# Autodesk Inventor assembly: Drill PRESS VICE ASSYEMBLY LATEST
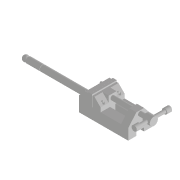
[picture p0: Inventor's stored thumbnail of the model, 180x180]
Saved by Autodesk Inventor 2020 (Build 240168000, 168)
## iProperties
Created: 2019-04
Part Number: Drill PRESS VICE ASSYEMBLY LATEST
Document SubType Name: Assembly
Designer: LENOVO-CADCIM
Author: LENOVO-CADCIM
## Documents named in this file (9)
- D:\Autodesk Inventor_2020\c10\c10_Inv_2019_tut\c10_Inv_tut_2019\c10_tut02_inv\Drill Press Vice\Drill Press Vice\Drill PRESS VICE ASSYEMBLY LATEST.iam
- D:\Autodesk Inventor_2020\c10\c10_Inv_2019_tut\c10_Inv_tut_2019\c10_tut02_inv\Drill Press Vice\Drill Press Vice\Base.ipt
- D:\Autodesk Inventor_2020\c10\c10_Inv_2019_tut\c10_Inv_tut_2019\c10_tut02_inv\Drill Press Vice\Drill Press Vice\Movable Jaw.ipt
- D:\Autodesk Inventor_2020\c10\c10_Inv_2019_tut\c10_Inv_tut_2019\c10_tut02_inv\Drill Press Vice\Drill Press Vice\Jaw Face.ipt
- D:\Autodesk Inventor_2020\c10\c10_Inv_2019_tut\c10_Inv_tut_2019\c10_tut02_inv\Drill Press Vice\Drill Press Vice\Cap Screw.ipt
- D:\Autodesk Inventor_2020\c10\c10_Inv_2019_tut\c10_Inv_tut_2019\c10_tut02_inv\Drill Press Vice\Drill Press Vice\Clamp Screw Handle.ipt
- D:\Autodesk Inventor_2020\c10\c10_Inv_2019_tut\c10_Inv_tut_2019\c10_tut02_inv\Drill Press Vice\Drill Press Vice\Clamp Screw.ipt
- D:\Autodesk Inventor_2020\c10\c10_Inv_2019_tut\c10_Inv_tut_2019\c10_tut02_inv\Drill Press Vice\Drill Press Vice\Safety Handle.ipt
- D:\Autodesk Inventor_2020\c10\c10_Inv_2019_tut\c10_Inv_tut_2019\c10_tut02_inv\Drill Press Vice\Drill Press Vice\Handle Stop.ipt
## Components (13 placed, 8 different names)
1. Base:1 — Mate:1, Mate:2, Insert:1, Insert:4, Insert:5, Mate:3, Mate:6, Mate:7
2. Movable Jaw:1 — Mate:1, Mate:2, Insert:2, Insert:3, Insert:6, Insert:7, Mate:4
3. Jaw Face:1 — Insert:1, Mate:8
4. Jaw Face:2 — Insert:2, Insert:3, Mate:8
5. Cap Screw:1 — Insert:4
6. Cap Screw:2 — Insert:7
7. Cap Screw:3 — Insert:5
8. Cap Screw:4 — Insert:6
9. Clamp Screw Handle:1 — Mate:5, Insert:8, Insert:9
10. Clamp Screw:1 — Mate:3, Mate:4, Mate:5
11. Safety Handle:1 — Mate:6, Mate:7
12. Handle Stop:1 — Insert:9
13. Handle Stop:2 — Insert:8
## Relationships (17: Insert 9, Mate 8)
- Mate:1: Base:1 ↔ Movable Jaw:1
- Mate:2: Base:1 ↔ Movable Jaw:1
- Insert:1: Base:1 ↔ Jaw Face:1
- Insert:2: Movable Jaw:1 ↔ Jaw Face:2
- Insert:3: Movable Jaw:1 ↔ Jaw Face:2
- Insert:4: Base:1 ↔ Cap Screw:1
- Insert:5: Base:1 ↔ Cap Screw:3
- Insert:6: Movable Jaw:1 ↔ Cap Screw:4
- Insert:7: Movable Jaw:1 ↔ Cap Screw:2
- Mate:3: Base:1 ↔ Clamp Screw:1
- Mate:4: Movable Jaw:1 ↔ Clamp Screw:1
- Mate:5: Clamp Screw Handle:1 ↔ Clamp Screw:1
- Mate:6: Base:1 ↔ Safety Handle:1
- Mate:7: Base:1 ↔ Safety Handle:1
- Mate:8: Jaw Face:1 ↔ Jaw Face:2
- Insert:8: Clamp Screw Handle:1 ↔ Handle Stop:2
- Insert:9: Clamp Screw Handle:1 ↔ Handle Stop:1
